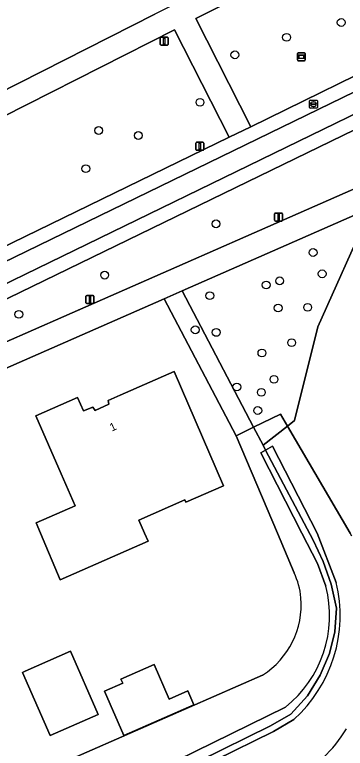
# Model space of a CAD drawing. Extents: x 162417 to 163722, y 384268 to 385417.
# Drawn here: x 163601.3 to 163642.7, y 384723.1 to 384814.8 of the extents above; entities that cross this region are included whole.
import ezdxf

# ---------------------------------------------------------------- set-up
doc = ezdxf.new("R2010")
doc.units = 0
for name, color, linetype in [('IMGEO_Berm_groen', 7, 'Continuous'), ('IMGEO_Boom', 7, 'Continuous'), ('IMGEO_Erf', 7, 'Continuous'), ('IMGEO_Groenvoorziening', 7, 'Continuous'), ('IMGEO_Hek', 7, 'Continuous'), ('IMGEO_Informatiebord', 7, 'Continuous'), ('IMGEO_Lichtmast', 7, 'Continuous'), ('IMGEO_Pand', 7, 'Continuous'), ('IMGEO_Pand_nummerreeks', 7, 'Continuous'), ('IMGEO_Rijbaan_lokaal_gesloten', 7, 'Continuous'), ('IMGEO_Rioolput', 7, 'Continuous'), ('IMGEO_Voetpad_open', 7, 'Continuous')]:
    doc.layers.add(name, color=color, linetype=linetype)

msp = doc.modelspace()

# ---------------------------------------------------------------- linework, layer by layer
at = {"layer": 'IMGEO_Berm_groen'}
msp.add_lwpolyline([(163659.841, 384768.233), (163664.204, 384793.9), (163662.207, 384797.874), (163661.604, 384797.609), (163648.619, 384791.889), (163647.386, 384791.328), (163645.894, 384790.674), (163645.701, 384790.242), (163639.223, 384775.822), (163636.309, 384764.095), (163635.43, 384763.407), (163643.262, 384750), (163643.454, 384749.672)], dxfattribs=at)
msp.add_arc((163628.593, 384734.004), 16.527, 296.92248, 329.29554, dxfattribs=at)
at = {"layer": 'IMGEO_Boom'}
for centre in [(163642.158, 384813.845), (163635.327, 384811.983), (163628.861, 384809.799), (163624.503, 384803.867), (163611.835, 384800.347), (163616.791, 384799.72), (163610.222, 384795.57), (163626.507, 384788.681), (163638.649, 384785.092), (163612.576, 384782.269), (163639.777, 384782.434), (163632.779, 384781.044), (163634.461, 384781.554), (163625.728, 384779.702), (163634.268, 384778.156), (163637.966, 384778.239), (163601.852, 384777.368), (163623.907, 384775.436), (163626.527, 384775.112), (163635.965, 384773.827), (163632.245, 384772.542), (163633.75, 384769.245), (163629.108, 384768.293), (163632.176, 384767.617), (163631.727, 384765.348)]:
    msp.add_circle(centre, 0.489, dxfattribs=at)
at = {"layer": 'IMGEO_Erf'}
for points in [[(163552.107, 384845.87), (163579.211, 384794.807), (163618.849, 384814.904)], [(163629.015, 384762.166), (163620.015, 384779.318), (163597.399, 384769.395), (163594.343, 384768.075), (163593.786, 384767.999), (163590.832, 384766.733), (163590.746, 384767.004), (163574.261, 384760.525), (163544.894, 384751.808), (163508.033, 384740.986), (163472.811, 384730.645), (163473.066, 384729.467), (163473.133, 384728.955)], [(163636.275, 384745.077), (163634.184, 384750), (163629.015, 384762.166)], [(163469.126, 384699.679), (163464.448, 384690.322), (163467.143, 384691.226), (163484.237, 384684.113), (163500, 384688.721), (163580.363, 384712.213), (163579.87, 384714.065), (163582.836, 384714.854), (163583.309, 384713.074), (163598.787, 384717.599), (163632.332, 384732.289)]]:
    msp.add_lwpolyline(points, dxfattribs=at)
for points in [[(163614.539, 384767.281), (163621.256, 384770.234), (163627.459, 384755.953), (163622.736, 384753.877), (163622.608, 384754.17), (163616.859, 384751.644), (163617.582, 384750), (163618.01, 384749.026), (163607.025, 384744.198), (163604.563, 384750), (163604.015, 384751.292), (163608.899, 384753.453), (163607.141, 384757.448), (163603.954, 384764.689), (163609.201, 384766.988), (163609.928, 384765.314), (163611.1, 384765.783), (163611.408, 384765.362), (163613.093, 384766.143), (163613.017, 384766.617)], [(163602.32, 384732.626), (163602.643, 384732.791), (163608.293, 384735.252), (163611.751, 384727.345), (163605.774, 384724.731)], [(163623.735, 384728.555), (163614.978, 384724.718), (163612.546, 384730.268), (163614.836, 384731.272), (163614.619, 384731.766), (163618.777, 384733.589), (163620.664, 384729.284), (163622.972, 384730.295)]]:
    msp.add_lwpolyline(points, close=True, dxfattribs=at)
for centre, radius, start, end in [((163627.544, 384741.008), 9.633, 5.5836, 24.98854), ((163626.771, 384741.073), 10.397, 302.33713, 4.80842)]:
    msp.add_arc(centre, radius, start, end, dxfattribs=at)
at = {"layer": 'IMGEO_Groenvoorziening'}
for points in [[(163647.107, 384826.065), (163646.209, 384825.591), (163645.189, 384825.054), (163624.002, 384814.334), (163630.865, 384800.823), (163650.563, 384810.473), (163653.281, 384811.762), (163654.204, 384812.214)], [(163649.198, 384795.433), (163653.708, 384797.347), (163653.97, 384796.839), (163660.571, 384799.786), (163656.997, 384806.824), (163656.016, 384806.343), (163652.84, 384804.821), (163599.019, 384778.689), (163599.504, 384777.643), (163598.466, 384777.1), (163599.879, 384773.749)], [(163622.273, 384780.309), (163631.205, 384763.249), (163634.555, 384764.905), (163635.43, 384763.407), (163636.309, 384764.095), (163639.223, 384775.822), (163645.701, 384790.242), (163645.894, 384790.674)], [(163620.015, 384779.318), (163629.015, 384762.166), (163631.205, 384763.249), (163622.273, 384780.309)], [(163632.38, 384761.02), (163635.43, 384763.407), (163634.555, 384764.905), (163631.205, 384763.249)]]:
    msp.add_lwpolyline(points, close=True, dxfattribs=at)
for points in [[(163585.393, 384778.896), (163588.913, 384780.464), (163589.864, 384780.875), (163628.147, 384799.526), (163621.295, 384812.929), (163575.222, 384789.612), (163577.885, 384783.374), (163577.57, 384783.198), (163577.982, 384782.302)], [(163640.239, 384743.378), (163639.189, 384746.21), (163637.25, 384750), (163632.102, 384760.065), (163632.707, 384760.4), (163632.38, 384761.02), (163631.205, 384763.249), (163629.015, 384762.166), (163634.184, 384750), (163636.275, 384745.077)], [(163643.454, 384749.672), (163643.262, 384750), (163635.43, 384763.407), (163632.38, 384761.02), (163632.707, 384760.4), (163633.582, 384760.884), (163639.147, 384750), (163641.537, 384743.873)], [(163641.537, 384743.873), (163639.147, 384750), (163633.582, 384760.884), (163632.707, 384760.4), (163638.651, 384749.125), (163639.922, 384746.465), (163640.909, 384743.639), (163641.587, 384740.629), (163641.372, 384737.696), (163640.699, 384734.987), (163639.513, 384732.281), (163637.93, 384729.671), (163635.85, 384727.388), (163633.297, 384725.957), (163606.414, 384712.68), (163603.1, 384711.166), (163598.253, 384709.249), (163485.375, 384676.903), (163482.27, 384677.584), (163479.995, 384678.63), (163479.719, 384678.022), (163486.222, 384675.932), (163500, 384679.941), (163592.683, 384706.906)], [(163485.375, 384676.903), (163598.253, 384709.249), (163603.1, 384711.166), (163606.414, 384712.68), (163633.297, 384725.957), (163635.85, 384727.388), (163637.93, 384729.671), (163639.513, 384732.281), (163640.699, 384734.987), (163641.372, 384737.696), (163641.587, 384740.629), (163640.909, 384743.639), (163639.922, 384746.465), (163638.651, 384749.125), (163632.707, 384760.4), (163632.102, 384760.065), (163637.25, 384750), (163639.189, 384746.21), (163640.239, 384743.378)], [(163632.332, 384732.289), (163598.787, 384717.599), (163583.309, 384713.074), (163583.612, 384711.932), (163580.647, 384711.144), (163580.363, 384712.213), (163500, 384688.721), (163484.237, 384684.113), (163467.143, 384691.226), (163469.49, 384683.461), (163479.995, 384678.63), (163480.345, 384679.402), (163485.499, 384677.78), (163500, 384682.013), (163598.068, 384710.642)], [(163635.189, 384728.274), (163608.118, 384714.995)], [(163608.118, 384714.995), (163635.189, 384728.274)], [(163636.226, 384726.725), (163633.673, 384725.224), (163604.506, 384710.893)], [(163604.506, 384710.893), (163633.673, 384725.224), (163636.226, 384726.725)]]:
    msp.add_lwpolyline(points, dxfattribs=at)
for centre, radius, start, end in [((163627.544, 384741.008), 9.633, 5.5836, 24.98854), ((163624.526, 384739.745), 17.504, 311.94261, 13.64027), ((163624.526, 384739.745), 17.504, 311.94261, 13.64027), ((163626.072, 384739.718), 14.632, 308.54181, 14.48363), ((163626.072, 384739.718), 14.632, 308.54181, 14.48363), ((163626.771, 384741.073), 10.397, 302.33713, 4.80842), ((163628.593, 384734.004), 16.527, 296.92248, 329.29554)]:
    msp.add_arc(centre, radius, start, end, dxfattribs=at)
at = {"layer": 'IMGEO_Hek'}
for points in [[(163629.015, 384762.166), (163620.015, 384779.318)], [(163631.205, 384763.249), (163632.38, 384761.02)], [(163632.707, 384760.4), (163638.651, 384749.125), (163639.922, 384746.465), (163640.909, 384743.639), (163641.587, 384740.629), (163641.372, 384737.696), (163640.699, 384734.987), (163639.513, 384732.281), (163637.93, 384729.671), (163635.85, 384727.388), (163633.297, 384725.957), (163606.414, 384712.68), (163603.1, 384711.166), (163598.253, 384709.249), (163485.375, 384676.903), (163482.27, 384677.584), (163479.995, 384678.63)], [(163632.38, 384761.02), (163632.707, 384760.4)]]:
    msp.add_lwpolyline(points, dxfattribs=at)
at = {"layer": 'IMGEO_Informatiebord'}
for p, q in [((163636.679, 384809.158), (163636.679, 384809.958)), ((163636.679, 384809.958), (163636.679, 384809.158)), ((163636.779, 384810.058), (163637.569, 384810.058)), ((163637.569, 384810.058), (163636.779, 384810.058)), ((163637.669, 384809.958), (163637.669, 384809.158)), ((163637.669, 384809.158), (163637.669, 384809.958)), ((163637.569, 384809.058), (163636.779, 384809.058)), ((163636.779, 384809.058), (163637.569, 384809.058))]:
    msp.add_line(p, q, dxfattribs=at)
for points in [[(163636.78, 384809.79), (163637.568, 384809.79), (163637.568, 384809.326), (163636.78, 384809.326), (163636.78, 384809.79)], [(163636.845, 384809.725), (163636.845, 384809.391), (163637.503, 384809.391), (163637.503, 384809.725), (163636.845, 384809.725)]]:
    msp.add_lwpolyline(points, dxfattribs=at)
for centre, start, end in [((163636.779, 384809.958), 90, 180), ((163636.779, 384809.958), 90, 180), ((163637.569, 384809.958), 0, 90), ((163637.569, 384809.958), 360, 90), ((163636.779, 384809.158), 180, 270), ((163636.779, 384809.158), 180, 270), ((163637.569, 384809.158), 270, 0), ((163637.569, 384809.158), 270, 0)]:
    msp.add_arc(centre, 0.1, start, end, dxfattribs=at)
at = {"layer": 'IMGEO_Lichtmast'}
for p, q in [((163619.537, 384811.107), (163619.537, 384811.907)), ((163619.537, 384811.907), (163619.537, 384811.107)), ((163619.637, 384812.007), (163620.427, 384812.007)), ((163620.427, 384812.007), (163619.637, 384812.007)), ((163620.527, 384811.907), (163620.527, 384811.107)), ((163620.527, 384811.107), (163620.527, 384811.907)), ((163620.427, 384811.007), (163619.637, 384811.007)), ((163619.637, 384811.007), (163620.427, 384811.007)), ((163623.984, 384797.968), (163623.984, 384798.768)), ((163623.984, 384798.768), (163623.984, 384797.968)), ((163624.084, 384798.868), (163624.874, 384798.868)), ((163624.874, 384798.868), (163624.084, 384798.868)), ((163624.974, 384798.768), (163624.974, 384797.968)), ((163624.974, 384797.968), (163624.974, 384798.768)), ((163624.874, 384797.868), (163624.084, 384797.868)), ((163624.084, 384797.868), (163624.874, 384797.868)), ((163633.836, 384789.124), (163633.836, 384789.924)), ((163633.836, 384789.924), (163633.836, 384789.124)), ((163633.936, 384790.024), (163634.726, 384790.024)), ((163634.726, 384790.024), (163633.936, 384790.024)), ((163634.826, 384789.924), (163634.826, 384789.124)), ((163634.826, 384789.124), (163634.826, 384789.924)), ((163634.726, 384789.024), (163633.936, 384789.024)), ((163633.936, 384789.024), (163634.726, 384789.024)), ((163610.247, 384778.828), (163610.247, 384779.628)), ((163610.247, 384779.628), (163610.247, 384778.828)), ((163610.347, 384779.728), (163611.137, 384779.728)), ((163611.137, 384779.728), (163610.347, 384779.728)), ((163611.237, 384779.628), (163611.237, 384778.828)), ((163611.237, 384778.828), (163611.237, 384779.628)), ((163611.137, 384778.728), (163610.347, 384778.728)), ((163610.347, 384778.728), (163611.137, 384778.728))]:
    msp.add_line(p, q, dxfattribs=at)
for points in [[(163619.957, 384811.882), (163620.107, 384811.882), (163620.107, 384811.132), (163619.957, 384811.132), (163619.957, 384811.882)], [(163624.404, 384798.743), (163624.554, 384798.743), (163624.554, 384797.993), (163624.404, 384797.993), (163624.404, 384798.743)], [(163634.256, 384789.899), (163634.406, 384789.899), (163634.406, 384789.149), (163634.256, 384789.149), (163634.256, 384789.899)], [(163610.667, 384779.603), (163610.817, 384779.603), (163610.817, 384778.853), (163610.667, 384778.853), (163610.667, 384779.603)]]:
    msp.add_lwpolyline(points, dxfattribs=at)
for centre, start, end in [((163619.637, 384811.907), 90, 180), ((163619.637, 384811.907), 90, 180), ((163620.427, 384811.907), 0, 90), ((163620.427, 384811.907), 360, 90), ((163619.637, 384811.107), 180, 270), ((163619.637, 384811.107), 180, 270), ((163620.427, 384811.107), 270, 0), ((163620.427, 384811.107), 270, 0), ((163624.084, 384798.768), 90, 180), ((163624.084, 384798.768), 90, 180), ((163624.874, 384798.768), 0, 90), ((163624.874, 384798.768), 360, 90), ((163624.084, 384797.968), 180, 270), ((163624.084, 384797.968), 180, 270), ((163624.874, 384797.968), 270, 0), ((163624.874, 384797.968), 270, 0), ((163633.936, 384789.924), 90, 180), ((163633.936, 384789.924), 90, 180), ((163634.726, 384789.924), 0, 90), ((163634.726, 384789.924), 360, 90), ((163633.936, 384789.124), 180, 270), ((163633.936, 384789.124), 180, 270), ((163634.726, 384789.124), 270, 0), ((163634.726, 384789.124), 270, 0), ((163610.347, 384779.628), 90, 180), ((163610.347, 384779.628), 90, 180), ((163611.137, 384779.628), 0, 90), ((163611.137, 384779.628), 360, 90), ((163610.347, 384778.828), 180, 270), ((163610.347, 384778.828), 180, 270), ((163611.137, 384778.828), 270, 0), ((163611.137, 384778.828), 270, 0)]:
    msp.add_arc(centre, 0.1, start, end, dxfattribs=at)
at = {"layer": 'IMGEO_Pand'}
for points in [[(163614.539, 384767.281), (163613.017, 384766.617), (163613.093, 384766.143), (163611.408, 384765.362), (163611.1, 384765.783), (163609.928, 384765.314), (163609.201, 384766.988), (163603.954, 384764.689), (163607.141, 384757.448), (163608.899, 384753.453), (163604.015, 384751.292), (163604.563, 384750), (163607.025, 384744.198), (163618.01, 384749.026), (163617.582, 384750), (163616.859, 384751.644), (163622.608, 384754.17), (163622.736, 384753.877), (163627.459, 384755.953), (163621.256, 384770.234)], [(163602.32, 384732.626), (163605.774, 384724.731), (163611.751, 384727.345), (163608.293, 384735.252), (163602.643, 384732.791)], [(163623.735, 384728.555), (163622.972, 384730.295), (163620.664, 384729.284), (163618.777, 384733.589), (163614.619, 384731.766), (163614.836, 384731.272), (163612.546, 384730.268), (163614.978, 384724.718)]]:
    msp.add_lwpolyline(points, close=True, dxfattribs=at)
at = {"layer": 'IMGEO_Rijbaan_lokaal_gesloten'}
for points in [[(163654.065, 384810.197), (163653.281, 384811.762), (163650.563, 384810.473), (163630.865, 384800.823), (163628.147, 384799.526), (163589.864, 384780.875), (163590.625, 384779.354), (163651.434, 384808.887)], [(163654.065, 384810.197), (163651.434, 384808.887), (163590.625, 384779.354), (163591.695, 384777.073), (163652.384, 384806.57), (163655.201, 384807.971)], [(163591.695, 384777.073), (163592.49, 384775.548), (163599.019, 384778.689), (163652.84, 384804.821), (163656.016, 384806.343), (163655.201, 384807.971), (163652.384, 384806.57)]]:
    msp.add_lwpolyline(points, close=True, dxfattribs=at)
at = {"layer": 'IMGEO_Rioolput'}
for p, q in [((163638.185, 384803.211), (163638.185, 384804.063)), ((163638.26, 384804.137), (163639.112, 384804.137)), ((163638.444, 384803.631), (163638.444, 384803.643)), ((163638.882, 384803.594), (163638.484, 384803.594)), ((163638.487, 384803.68), (163638.885, 384803.68)), ((163638.696, 384803.357), (163638.671, 384803.357)), ((163638.673, 384803.917), (163638.698, 384803.917)), ((163638.928, 384803.643), (163638.928, 384803.631)), ((163639.186, 384804.063), (163639.186, 384803.211)), ((163639.112, 384803.137), (163638.26, 384803.137))]:
    msp.add_line(p, q, dxfattribs=at)
for points in [[(163638.185, 384803.211), (163638.185, 384804.063)], [(163638.26, 384804.137), (163639.112, 384804.137)], [(163639.186, 384804.063), (163639.186, 384803.211)], [(163639.112, 384803.137), (163638.26, 384803.137)]]:
    msp.add_lwpolyline(points, dxfattribs=at)
for centre, radius, start, end in [((163638.262, 384804.061), 0.0765, 91.55205, 178.44795), ((163638.262, 384804.061), 0.0765, 91.55205, 178.44795), ((163638.484, 384803.64), 0.0403, 85.87752, 175.75265), ((163638.481, 384803.63), 0.0366, 178.93798, 274.71019), ((163638.885, 384803.637), 0.043, 264.86636, 352.45326), ((163638.889, 384803.642), 0.0386, 1.73085, 96.63898), ((163639.11, 384804.061), 0.0765, 1.55205, 88.44795), ((163639.11, 384804.061), 0.0765, 1.55205, 88.44795), ((163638.262, 384803.213), 0.0765, 181.55205, 268.44795), ((163638.262, 384803.213), 0.0765, 181.55205, 268.44795), ((163639.11, 384803.213), 0.0765, 271.55205, 358.44795), ((163639.11, 384803.213), 0.0765, 271.55205, 358.44795)]:
    msp.add_arc(centre, radius, start, end, dxfattribs=at)
for centre, major_axis, ratio, start_param, end_param in [((163638.672, 384803.637), (-0.387, 0.002), 0.722429, 4.712389, 7.853982), ((163638.697, 384803.637), (-0.39, 0.002), 0.717154, 1.570796, 4.712389)]:
    msp.add_ellipse(centre, major_axis=major_axis, ratio=ratio, start_param=start_param, end_param=end_param, dxfattribs=at)
at = {"layer": 'IMGEO_Voetpad_open'}
msp.add_lwpolyline([(163621.295, 384812.929), (163628.147, 384799.526), (163630.865, 384800.823), (163624.002, 384814.334), (163645.189, 384825.054), (163646.209, 384825.591), (163644.977, 384828.162), (163641.486, 384826.348), (163641.667, 384825.959), (163626.635, 384818.288), (163626.367, 384818.629), (163618.849, 384814.904), (163579.211, 384794.807), (163577.006, 384793.682), (163576.893, 384793.832), (163573.858, 384792.219), (163573.909, 384792.119), (163575.222, 384789.612)], close=True, dxfattribs=at)
for points in [[(163649.198, 384795.433), (163599.879, 384773.749), (163598.466, 384777.1), (163594.629, 384775.278), (163595.959, 384772.234), (163593.149, 384771.03), (163591.909, 384773.956), (163588.13, 384772.356), (163589.443, 384769.361), (163573.24, 384763.319), (163569.077, 384762.111), (163567.982, 384765.62), (163564.418, 384764.577), (163565.429, 384761.073), (163543.448, 384754.524), (163542.381, 384758.018), (163538.627, 384756.959), (163539.698, 384753.429), (163537.254, 384752.674), (163510.906, 384744.904)], [(163508.033, 384740.986), (163544.894, 384751.808), (163574.261, 384760.525), (163590.746, 384767.004), (163590.832, 384766.733), (163593.786, 384767.999), (163594.343, 384768.075), (163597.399, 384769.395), (163620.015, 384779.318), (163622.273, 384780.309), (163645.894, 384790.674)]]:
    msp.add_lwpolyline(points, dxfattribs=at)

# ---------------------------------------------------------------- texts
at = {"layer": 'IMGEO_Pand_nummerreeks'}
msp.add_text('1', height=1, rotation=24.86779, dxfattribs=at).set_placement((163613.483, 384762.708))

doc.saveas('drawing.dxf')
